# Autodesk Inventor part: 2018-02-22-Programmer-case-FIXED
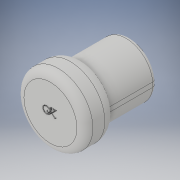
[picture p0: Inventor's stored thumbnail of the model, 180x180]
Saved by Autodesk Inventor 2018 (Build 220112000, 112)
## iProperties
Created: 2018-02
Part Number: 2018-02-22-Programmer-case-FIXED
Material: Generic
Document SubType Name: Modeling
Designer: katin
Density: 1 g/cm^3
Appearance: Default
Author: katin
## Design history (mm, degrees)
sketch "Sketch1"
  geometry: L1 (0, 0)-(20, 0); L2 (20, 0)-(20, -56.34); L3 (20, -56.34)-(0, -56.34); L4 (0, -56.34)-(0, 0); L5 (0, 0)-(3.95, 0); L6 (3.95, 0)-(3.95, -10.13); L7 (3.95, -10.13)-(0, -10.13); L8 (0, -10.13)-(0, 0); L9 (20, 0)-(16.05, 0); L10 (16.05, 0)-(16.05, -10.13); L11 (16.05, -10.13)-(20, -10.13); L12 (20, -10.13)-(20, 0)
  constraints: 24 end point, 6 parallel, 3 horizontal, 3 perpendicular
  dimensions: "d0" = 20 distance of L2.end L3.end; "d1" = 56.34 distance of L1.end L2.end; "d2" = 3.95 distance of L6.end L7.end; "d3" = 10.13 distance of L5.end L6.end; "d4" = 3.95 distance of L11.end L10.end; "d5" = 10.13 distance of L10.end L9.end
extrude "Extrusion1" new body sketch "Sketch1" distance "d6" = 2.8; taper "d7" = 0 deg
sketch "Sketch2"
  geometry: L1 (-16.05, 10.13)-(-16.05, 0) reference; L2 (-16.05, 0)-(-3.95, 0); L3 (-3.95, 0)-(-3.95, 46.34); L4 (-3.95, 46.34)-(-16.05, 46.34); L5 (-16.05, 46.34)-(-16.05, 0); L6 (-16.05, 46.34)-(-17.58, 46.34); L7 (-17.58, 46.34)-(-17.58, 9.13); L8 (-17.58, 9.13)-(-16.05, 9.13); L9 (-16.05, 9.13)-(-16.05, 46.34); L10 (-3.95, 46.34)-(-2.42, 46.34); L11 (-2.42, 46.34)-(-2.42, 9.13); L12 (-2.42, 9.13)-(-3.95, 9.13); L13 (-3.95, 9.13)-(-3.95, 46.34); 1 further point
  constraints: 24 end point, 6 parallel, 3 horizontal, 3 perpendicular
  dimensions: "d8" = 12.1 distance of L4.end L3.end; "d9" = 46.34 distance of L3.end L2.end; "d10" = 1.53 distance of L8.end L7.end; "d11" = 37.21 distance of L7.end L6.end; "d12" = 1.53 distance of L11.end L12.end; "d13" = 37.21 distance of L10.end L11.end
extrude "Extrusion2" cut sketch "Sketch2" distance "d14" = 2.1; taper "d15" = 0 deg
sketch "Sketch3"
  geometry: L1 (0, 0)-(-10.2, 0); L2 (-10.2, 0)-(-10.2, 2.8); L3 (-10.2, 2.8)-(0, 2.8); L4 (0, 2.8)-(0, 0); L5 (16.05, 0)-(20, 0) reference; L6 (20, 2.8)-(20, 0); L7 (20, 2.8)-(17.58, 2.8) reference; L8 (20, 2.8)-(0, 2.8); L9 (0, 0)-(20, 0); L10 (20, 0)-(20, -16); L11 (20, -16)-(0, -16); L12 (0, -16)-(0, 0); L13 (20, 0)-(30.2, 0); L14 (30.2, 0)-(30.2, 2.8); L15 (30.2, 2.8)-(20, 2.8); L16 (20, 2.8)-(20, 0); L17 (0, 2.8)-(1.5, 2.8); L18 (0, 2.8)-(20, 2.8); L19 (20, 2.8)-(18.5, 2.8); L20 (18.5, 2.8)-(1.5, 2.8); L21 (0, 2.8)-(20, 2.8); L22 (20, 2.8)-(20, 18.8); L23 (20, 18.8)-(0, 18.8); L24 (0, 18.8)-(0, 2.8); L25 (0, 3.175)-(-10.163, 3.175); L26 (20, 3.175)-(30.162, 3.175); L27 (0, 0)-(0, -0.375); L28 (0, -0.375)-(-10.163, -0.375); L29 (20, -0.375)-(30.162, -0.375); C1 r 26.5 at (10, 1.4); A1 r 20.24 centre (10, 1.4) between (-10.163, 3.175) and (30.162, 3.175)
  constraints: 54 end point, 8 horizontal, 8 parallel, 6 point on line, 4 perpendicular, 4 point on circle, 2 centre point, 1 coincident
  dimensions: "d16" = 10.2 distance of L2.end L3.end; "d17" = 2.8 distance of L1.end L2.end; "d21" = 20 distance of L10.end L11.end; "d22" = 16 distance of L9.end L10.end; "d23" = 10.2 distance of L15.end L14.end; "d24" = 2.8 distance of L14.end L13.end; "d32" = 20 distance of L23.end L22.end; "d33" = 16 distance of L22.end L21.end; "d34" = 0.375 distance of L1.start L27.end; "d35" = 90 deg angle of L27 L28; "d36" = 53 diameter of C1
extrude "Extrusion3" join sketch "Sketch3" distance "d37" = 56.34; taper "d38" = 0 deg
sketch "Sketch4"
  geometry: L1 (0, 0)-(-5, 0); L2 (-5, 0)-(-5, 2.8); L3 (-5, 2.8)-(0, 2.8); L4 (0, 2.8)-(0, 0); L5 (16.05, 0)-(20, 0) reference; L6 (20, 0)-(25, 0); L7 (25, 0)-(25, 2.8); L8 (25, 2.8)-(20, 2.8); L9 (20, 2.8)-(20, 0)
  constraints: 16 end point, 4 parallel, 2 horizontal, 2 perpendicular
  dimensions: "d39" = 5 distance of L2.end L3.end; "d40" = 2.8 distance of L1.end L2.end; "d41" = 5 distance of L8.end L7.end; "d42" = 2.8 distance of L7.end L6.end
extrude "Extrusion4" join sketch "Sketch4" distance "d43" = 46.21; taper "d44" = 0 deg
sketch "Sketch5"
  geometry: C1 r 26 at (-10, 1.4); C2 r 20.84 at (-10, 1.4); A1 r 20.24 centre (-10, 1.4) between (10.163, 3.175) and (-30.162, 3.175) reference; 1 further point
  constraints: 2 centre point, 2 coincident
  dimensions: "d45" = 52 diameter of C1; "d46" = 41.68 diameter of C2
sketch "Sketch6"
  geometry: L1 (-42.21, 2.8)-(-42.21, 0); L2 (-42.21, 0)-(-38.21, 0); L3 (-38.21, 0)-(-38.21, 2.8); L4 (-38.21, 2.8)-(-42.21, 2.8); L5 (-42.21, 2.8)-(-42.21, 0); 2 further points
  constraints: 10 end point, 2 parallel, 1 horizontal, 1 perpendicular
  dimensions: "d48" = 2.8 distance of L1.start L1.end; "d49" = 4 distance of L4.end L3.end
extrude "Extrusion5" cut sketch "Sketch6" distance "d50" = 5; taper "d51" = 0 deg
sketch "Sketch7"
  geometry: L1 (0, 0)-(46.21, 0) reference; L2 (46.21, 0)-(41.21, 0); L3 (41.21, 0)-(41.21, 2.8); L4 (41.21, 0)-(37.21, 0); L5 (37.21, 0)-(37.21, 2.8); L6 (37.21, 2.8)-(41.21, 2.8); L7 (41.21, 2.8)-(41.21, 0); 1 further point
  constraints: 12 end point, 2 horizontal, 2 parallel, 2 perpendicular
  dimensions: "d53" = 2.8 distance of L2.end L3.end; "d54" = 4 distance of L5.end L6.end; "d55" = 2.8 distance of L4.end L5.end
extrude "Extrusion6" cut sketch "Sketch7" distance "d56" = 5; taper "d57" = 0 deg
sketch "Sketch8"
  geometry: L1 (0, 3.175)-(-10.163, 3.175) reference; L2 (-10.163, 3.175)-(-5.754, 3.175); L3 (-10.163, -0.375)-(0, -0.375) reference; L4 (-5.754, -0.375)-(-10.163, -0.375); L5 (-10.163, -0.375)-(-5.754, -0.375); L6 (-5.754, 3.175)-(-5.754, -0.375); L7 (-10.163, 3.175)-(-5.754, 3.175); L8 (-5.754, 3.175)-(-5.754, -0.375); L9 (-5.754, -0.375)-(-10.163, -0.375); L10 (-5.754, 3.175)-(-10.163, 3.175); L11 (-10.163, -0.375)-(-5.754, -0.375); L12 (-5.754, 3.175)-(-10.163, 3.175); L13 (-10.163, 3.175)-(-5.754, 3.175); L14 (-5.754, -0.375)-(-10.163, -0.375); L15 (-10.163, 3.175)-(-5.754, 3.175); L16 (-10.163, -0.375)-(-5.754, -0.375); A1 r 20.24 centre (10, 1.4) between (30.162, 3.175) and (-10.163, 3.175) reference; A2 r 20.24 centre (10, 1.4) between (-10.163, -0.375) and (30.162, -0.375) reference; A3 r 20.24 centre (10, 1.4) between (-9.959, 4.763) and (-10.162, 3.175); A4 r 20.24 centre (10, 1.4) between (-10.163, 3.175) and (-10.162, 3.175); A5 r 1.635 centre (-10.163, 3.175) between (-10.259, 1.543) and (-10.163, 1.54); A6 r 20.241 centre (10, 1.4) between (-10.163, 3.175) and (-10.163, -0.375); A7 r 20.241 centre (10, 1.4) between (-10.194, 2.767) and (-10.163, 3.175); 1 further point
  constraints: 28 end point, 16 point on circle, 7 collinear, 5 centre point, 2 parallel, 2 perpendicular, 2 point on line, 1 coincident, 1 horizontal, 1 tangent
extrude "Extrusion7" join sketch "Sketch8" distance "d58" = 47.21; taper "d59" = 0 deg
sketch "Sketch9"
  geometry: L1 (-10.163, 3.175)-(25.753, 3.175); L2 (20, 3.175)-(30.162, 3.175) reference; L3 (25.753, 3.175)-(25.753, -0.375); L4 (20, -0.375)-(30.162, -0.375) reference; L5 (25.753, -0.375)-(30.162, -0.375); L6 (25.753, -0.375)-(25.753, 3.175); L7 (30.162, 3.175)-(25.753, 3.175); L8 (25.753, 3.175)-(30.162, 3.175); L9 (30.163, -0.375)-(25.753, -0.375); L10 (25.753, 3.175)-(30.162, 3.175); A1 r 20.24 centre (10, 1.4) between (30.162, 3.175) and (-10.163, 3.175) reference; A2 r 20.24 centre (10, 1.4) between (-10.163, -0.375) and (30.162, -0.375) reference; A3 r 20.24 centre (10, 1.4) between (30.162, 3.175) and (-10.163, -0.375); A4 r 20.24 centre (10, 1.4) between (30.162, 3.175) and (30.162, -0.375); A5 r 17.737 centre (12.494, 1.18) between (30.162, -0.375) and (30.163, -0.375); A6 r 20.241 centre (10, 1.4) between (30.163, -0.375) and (30.162, 3.175)
  constraints: 16 end point, 10 point on circle, 4 centre point, 4 collinear, 2 concentric, 2 point on line, 2 tangent, 1 horizontal
  dimensions: "d61" = 3.55 distance of L1.end L3.end
extrude "Extrusion8" join sketch "Sketch9" distance "d64" = 47.21; taper "d65" = 0 deg
sketch "Sketch10"
  geometry: L1 (-47.21, 0)-(-47.21, 3.55) reference; L2 (-47.21, 3.55)-(-42.21, 3.55); L3 (-42.21, 3.55)-(-42.21, 0); L4 (-42.21, 0)-(-47.21, 0); L5 (-47.21, 0)-(-47.21, 3.55); L6 (-42.21, 0)-(-38.21, 0); L7 (-38.21, 0)-(-38.21, 8); L8 (-38.21, 8)-(-42.21, 8); L9 (-42.21, 8)-(-42.21, 0); 1 further point
  constraints: 16 end point, 4 parallel, 2 horizontal, 2 perpendicular
  dimensions: "d66" = 5 distance of L3.end L4.end; "d67" = 3.55 distance of L2.end L3.end; "d68" = 4 distance of L8.end L7.end; "d69" = 8 distance of L7.end L6.end
extrude "Extrusion9" cut sketch "Sketch10" distance "d70" = 9; taper "d71" = 0 deg
sketch "Sketch11"
  geometry: L1 (42.21, 0)-(42.21, 3.55) reference; L2 (42.21, 3.55)-(38.21, 3.55); L3 (38.21, 3.55)-(38.21, 8); L4 (38.21, 8)-(42.21, 8); L5 (42.21, 8)-(42.21, 3.55); 1 further point
  constraints: 8 end point, 2 parallel, 1 horizontal, 1 perpendicular
  dimensions: "d72" = 4.45 distance of L2.end L3.end
extrude "Extrusion10" cut sketch "Sketch11" distance "d73" = 5; taper "d74" = 0 deg
sketch "Sketch12"
  geometry: L1 (47.21, 0)-(47.21, 3.55) reference; L2 (47.21, 3.55)-(42.21, 3.55); L3 (42.21, 3.55)-(42.21, 0); L4 (42.21, 0)-(47.21, 0); L5 (47.21, 0)-(47.21, 3.55); L6 (42.21, 3.55)-(47.21, 3.55) reference; L7 (42.21, 3.55)-(38.21, 3.55); L8 (38.21, 3.55)-(38.21, -4.45); L9 (38.21, -4.45)-(42.21, -4.45); L10 (42.21, -4.45)-(42.21, 3.55); 1 further point
  constraints: 16 end point, 4 parallel, 2 horizontal, 2 perpendicular
  dimensions: "d75" = 5 distance of L4.end L3.end; "d76" = 3.55 distance of L3.end L2.end; "d77" = 4 distance of L9.end L8.end; "d78" = 8 distance of L8.end L7.end
extrude "Extrusion11" cut sketch "Sketch12" distance "d79" = 5; taper "d80" = 0 deg
sketch "Sketch13"
  geometry: L1 (-42.21, 0)-(-47.21, 0) reference; L2 (-42.21, 0)-(-38.21, 0); L3 (-38.21, 0)-(-38.21, -4.45); L4 (-38.21, -4.45)-(-42.21, -4.45); L5 (-42.21, -4.45)-(-42.21, 0); 1 further point
  constraints: 8 end point, 2 parallel, 1 horizontal, 1 perpendicular
  dimensions: "d81" = 4 distance of L3.end L4.end; "d82" = 4.45 distance of L2.end L3.end
extrude "Extrusion12" cut sketch "Sketch13" distance "d83" = 5; taper "d84" = 0 deg
sketch "Sketch14"
  geometry: 1 further point
sketch "Sketch15"
  geometry: L1 (-5, 3.175)-(-9, 3.175) reference; L2 (-5.33, 3.175)-(-8.68, 3.175); L3 (-8.68, 3.175)-(-8.68, 0.175); L4 (-8.68, 0.175)-(-5.33, 0.175); L5 (-5.33, 0.175)-(-5.33, 3.175); 1 further point
  constraints: 8 end point, 2 parallel, 1 horizontal, 1 perpendicular, 1 point on line
  dimensions: "d85" = 3.35 distance of L4.end L3.end; "d86" = 3 distance of L3.end L2.end
extrude "Extrusion13" join sketch "Sketch15" distance "d87" = 8; taper "d89" = 0 deg; dims "d88" = 4, "d90" = 0
sketch "Sketch16"
  geometry: L1 (38.53, 2.8)-(41.88, 2.8) reference; L2 (38.53, 2.8)-(41.88, 2.8); L3 (41.88, 2.8)-(41.88, -0.2); L4 (41.88, -0.2)-(38.53, -0.2); L5 (38.53, -0.2)-(38.53, 2.8); 1 further point
  constraints: 8 end point, 2 parallel, 1 horizontal, 1 perpendicular
  dimensions: "d91" = 3.35 distance of L3.end L4.end; "d92" = 3 distance of L2.end L3.end
extrude "Extrusion14" join sketch "Sketch16" distance "d93" = 8; taper "d95" = 0 deg; dims "d94" = 3, "d96" = 0
extrude "Extrusion15" join sketch "Sketch5" distance "d97" = 20; taper "d98" = 0 deg
fillet "Fillet1" dims "d99" = 0.6
fillet "Fillet2" dims "d100" = 0.6
fillet "Fillet3" dims "d101" = 0.2
fillet "Fillet4" dims "d102" = 0.2
fillet "Fillet5" dims "d103" = 0.4
fillet "Fillet6" dims "d104" = 0.2
fillet "Fillet7" dims "d105" = 0.2
fillet "Fillet10" dims "d108" = 2.6
fillet "Fillet11" dims "d109" = 0.2
fillet "Fillet12" dims "d110" = 0.2
fillet "Fillet13" dims "d111" = 0.2
fillet "Fillet14" dims "d112" = 0.2
fillet "Fillet15" dims "d113" = 0.2
fillet "Fillet16" dims "d114" = 0.2
fillet "Fillet17" dims "d115" = 0.2
fillet "Fillet18" dims "d116" = 0.2
fillet "Fillet19" dims "d117" = 0.2
fillet "Fillet20" dims "d118" = 0.2
fillet "Fillet21" dims "d119" = 2.6
fillet "Fillet23" dims "d121" = 0.2
fillet "Fillet24" dims "d122" = 0.2
fillet "Fillet25" dims "d123" = 0.2
fillet "Fillet26" dims "d124" = 0.2
fillet "Fillet27" dims "d125" = 0.2
fillet "Fillet28" dims "d126" = 0.2
sketch "Sketch17"
  geometry: L1 (0.2, -0.375)-(0.5, -0.875) reference; L2 (0.2, -0.375)-(-20, -0.375); L3 (-20, -0.375)-(-20, -16.075); L4 (-20, -16.075)-(0.2, -16.075); L5 (0.2, -16.075)-(0.2, -0.375); L6 (-30.162, 3.175)-(-20, 3.175) reference; L7 (-20.2, 3.175)-(0, 3.175); L8 (0, 3.175)-(0, 18.875); L9 (0, 18.875)-(-20.2, 18.875); L10 (-20.2, 18.875)-(-20.2, 3.175); 1 further point
  constraints: 16 end point, 4 parallel, 2 horizontal, 2 perpendicular
  dimensions: "d127" = 20.2 distance of L4.end L3.end; "d128" = 15.7 distance of L3.end L2.end; "d129" = 20.2 distance of L9.end L8.end; "d130" = 15.7 distance of L8.end L7.end
extrude "Extrusion16" join sketch "Sketch17" distance "d131" = 9.13; taper "d132" = 0 deg
fillet "Fillet29" dims "d133" = 1.2
fillet "Fillet30" dims "d134" = 1.2
fillet "Fillet31" dims "d135" = 0.2
fillet "Fillet37" dims "d154" = 1.2
fillet "Fillet38" dims "d155" = 0.2
sketch "Sketch21"
  geometry: C1 r 26 at (0, 0); 1 further point
  constraints: 1 centre point
  dimensions: "d156" = 52 diameter of C1
sketch "Sketch22"
  geometry: C1 r 20.84 at (0, 0); 1 further point
  constraints: 1 centre point
  dimensions: "d157" = 41.68 diameter of C1
extrude "Extrusion20" join sketch "Sketch21" distance "d158" = 3.66; taper "d159" = 0 deg
extrude "Extrusion21" cut sketch "Sketch22" distance "d160" = 0.8; taper "d161" = 0 deg
fillet "Fillet39" dims "d162" = 10
fillet "Fillet40" dims "d163" = 6
fillet "Fillet41" dims "d164" = 3
fillet "Fillet42" dims "d165" = 0.2
sketch "Sketch23"
  geometry: L1 (-6.598, 3.871)-(4.762, 3.871); L2 (4.762, 3.871)-(4.763, -3.175); L3 (4.763, -3.175)-(-6.598, -3.175); L4 (-6.598, -3.175)-(-6.598, 3.871); 1 further point
  constraints: 2 other
extrude "Extrusion22" cut sketch "Sketch23" distance "d166" = 0.7; taper "d167" = 0 deg
fillet "Fillet43" dims "d168" = 0.2
fillet "Fillet44" dims "d169" = 0.2
fillet "Fillet45" dims "d170" = 0.2
fillet "Fillet46" dims "d171" = 0.2
fillet "Fillet47" dims "d172" = 0.2
fillet "Fillet48" dims "d173" = 0.2
fillet "Fillet49" dims "d174" = 0.2
fillet "Fillet50" dims "d175" = 0.2
body "Solid1"
